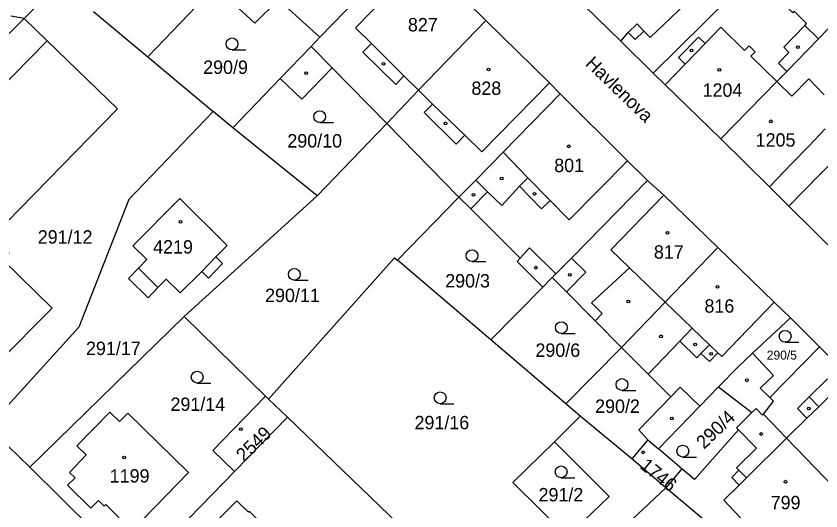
# Model space of a CAD drawing. Extents: x -679220 to -673243, y -1075091 to -1066557.
# Drawn here: x -676221 to -676118.6, y -1072209.4 to -1072146.6 of the extents above; entities that cross this region are included whole.
import ezdxf

# ---------------------------------------------------------------- set-up
doc = ezdxf.new("R2010")
doc.units = 0
for name, color, linetype in [('Hranice parcel', 7, 'Continuous'), ('Parcelní čísla', 7, 'Continuous'), ('Pop  PČ popisy', 7, 'Continuous'), ('Vnitřní kresba', 7, 'Continuous'), ('Značky budov', 7, 'Continuous'), ('Značky kultur', 7, 'Continuous')]:
    doc.layers.add(name, color=color, linetype=linetype)

msp = doc.modelspace()

# ---------------------------------------------------------------- linework, layer by layer
at = {"layer": 'Hranice parcel'}
for p, q in [((-676171, -1072137.54), (-676182.33, -1072149.26)), ((-676219.95, -1072146.87), (-676215.59, -1072142.43)), ((-676204.23, -1072151.76), (-676195.64, -1072142.82)), ((-676139.96, -1072153.8), (-676128.56, -1072142.56)), ((-676211.14, -1072145.98), (-676204.23, -1072151.76)), ((-676116.58, -1072147.02), (-676118.96, -1072149.46)), ((-676204.23, -1072151.76), (-676195.92, -1072158.68)), ((-676193.42, -1072160.74), (-676187.38, -1072154.49)), ((-676193.42, -1072160.74), (-676195.92, -1072158.68)), ((-676182.71, -1072169.41), (-676193.42, -1072160.74)), ((-676173.85, -1072160.2), (-676182.71, -1072169.41)), ((-676164.67, -1072169.55), (-676173.85, -1072160.2)), ((-676182.71, -1072169.41), (-676199.6, -1072184.73)), ((-676172.49, -1072177.56), (-676164.67, -1072169.55)), ((-676114.32, -1072179), (-676122.73, -1072170.71)), ((-676160.6, -1072187.71), (-676172.49, -1072177.56)), ((-676153.99, -1072180.99), (-676152.8, -1072179.78)), ((-676160.6, -1072187.71), (-676153.99, -1072180.99)), ((-676199.6, -1072184.73), (-676219.22, -1072203.87)), ((-676199.6, -1072184.73), (-676189.24, -1072194.84)), ((-676127.33, -1072189.39), (-676122.5, -1072184.89)), ((-676122.5, -1072184.89), (-676118.83, -1072188.57)), ((-676151.09, -1072195.83), (-676160.6, -1072187.71)), ((-676143.98, -1072188.65), (-676151.09, -1072195.83)), ((-676131.67, -1072193.67), (-676127.41, -1072196.92)), ((-676189.24, -1072194.84), (-676188.86, -1072195.21)), ((-676188.86, -1072195.21), (-676186.48, -1072197.53)), ((-676149.25, -1072197.4), (-676151.09, -1072195.83)), ((-676193.21, -1072204.43), (-676186.48, -1072197.53)), ((-676149.25, -1072197.4), (-676152.53, -1072200.63)), ((-676142.69, -1072202.8), (-676149.25, -1072197.4)), ((-676219.22, -1072203.87), (-676224.5, -1072198.75)), ((-676140.66, -1072200.39), (-676142.69, -1072202.8)), ((-676140.66, -1072200.39), (-676139.3, -1072201.54)), ((-676136.31, -1072204.07), (-676139.3, -1072201.54)), ((-676138.34, -1072206.48), (-676142.69, -1072202.8)), ((-676205.67, -1072217.2), (-676219.22, -1072203.87)), ((-676205.67, -1072217.2), (-676193.21, -1072204.43)), ((-676136.31, -1072204.07), (-676138.34, -1072206.48)), ((-676122.41, -1072219.9), (-676138.34, -1072206.48))]:
    msp.add_line(p, q, dxfattribs=at)
for points in [[(-676171, -1072137.54), (-676169.21, -1072139.25), (-676161.24, -1072147.11)], [(-676118.96, -1072149.46), (-676120.69, -1072147.75), (-676120.47, -1072147.52), (-676122.04, -1072145.93), (-676122.23, -1072146.15), (-676122.9, -1072145.47), (-676122.69, -1072145.28), (-676126.97, -1072140.99)], [(-676195.64, -1072142.82), (-676190.61, -1072147.46), (-676187.6, -1072144.46), (-676182.33, -1072149.26)], [(-676148.74, -1072145.24), (-676144.1, -1072149.74), (-676139.96, -1072153.8)], [(-676219.95, -1072146.87), (-676237.05, -1072163.9), (-676236.34, -1072164.6), (-676242.74, -1072171.08), (-676245.38, -1072174.32), (-676244.93, -1072177.99), (-676242.47, -1072175.5), (-676240.49, -1072177.48), (-676243.23, -1072180.25), (-676228.03, -1072195.27)], [(-676228.03, -1072195.27), (-676223.34, -1072190.59), (-676216.38, -1072183.67), (-676222.64, -1072177.53), (-676221.83, -1072176.7), (-676223.99, -1072174.59), (-676208.07, -1072158.35), (-676217, -1072149.7), (-676219.95, -1072146.87)], [(-676173.85, -1072160.2), (-676169.79, -1072155.99), (-676161.24, -1072147.11)], [(-676161.24, -1072147.11), (-676153.17, -1072155.05), (-676151.81, -1072156.45)], [(-676182.33, -1072149.26), (-676183.45, -1072150.42), (-676187.38, -1072154.49)], [(-676131.37, -1072162.17), (-676124.26, -1072154.89), (-676122.99, -1072153.59), (-676118.96, -1072149.46)], [(-676187.38, -1072154.49), (-676184.65, -1072157.13), (-676180.78, -1072153.14), (-676173.85, -1072160.2)], [(-676139.96, -1072153.8), (-676138.45, -1072155.3), (-676131.37, -1072162.17)], [(-676151.81, -1072156.45), (-676159.06, -1072163.86), (-676162.53, -1072167.4), (-676164.67, -1072169.55)], [(-676151.81, -1072156.45), (-676143.23, -1072164.95), (-676140.68, -1072167.47)], [(-676122.73, -1072170.71), (-676112.65, -1072160.42), (-676111.29, -1072159.03), (-676110.05, -1072157.72)], [(-676195.92, -1072158.68), (-676206.62, -1072169.88), (-676212.97, -1072186.08), (-676224.5, -1072198.75)], [(-676131.37, -1072162.17), (-676125.17, -1072168.27), (-676122.73, -1072170.71)], [(-676152.8, -1072179.78), (-676152.34, -1072179.32), (-676150.36, -1072177.31), (-676140.68, -1072167.47)], [(-676140.68, -1072167.47), (-676138.62, -1072169.32), (-676131.77, -1072175.96)], [(-676204.18, -1072182.37), (-676206.66, -1072179.88), (-676205.42, -1072178.57), (-676204.36, -1072177.5), (-676206.13, -1072175.75), (-676200.14, -1072169.72), (-676194.13, -1072175.69), (-676195.58, -1072177.16), (-676194.72, -1072178.01), (-676196.51, -1072179.84), (-676197.36, -1072178.99), (-676200.09, -1072181.72), (-676201.88, -1072179.97), (-676202.93, -1072181.04), (-676204.18, -1072182.37)], [(-676164.67, -1072169.55), (-676163.17, -1072171.05), (-676156.88, -1072177.31), (-676157.28, -1072177.76), (-676153.99, -1072180.99)], [(-676131.77, -1072175.96), (-676138.45, -1072182.9), (-676143.98, -1072188.65)], [(-676131.77, -1072175.96), (-676124.58, -1072182.9), (-676122.5, -1072184.89)], [(-676188.86, -1072195.21), (-676172.84, -1072177.27), (-676172.49, -1072177.56)], [(-676152.8, -1072179.78), (-676151, -1072181.59), (-676147.35, -1072185.26), (-676143.98, -1072188.65)], [(-676118.83, -1072188.57), (-676125.13, -1072195.02), (-676126.35, -1072193.81), (-676124.67, -1072192.24), (-676127.33, -1072189.39)], [(-676118.83, -1072188.57), (-676115.04, -1072192.36), (-676107.7, -1072199.66)], [(-676143.98, -1072188.65), (-676140.61, -1072192.04), (-676137.71, -1072194.95), (-676141.78, -1072199.14), (-676140.66, -1072200.39)], [(-676127.33, -1072189.39), (-676129.18, -1072191.11), (-676131.67, -1072193.67)], [(-676139.3, -1072201.54), (-676134.04, -1072196.12), (-676131.67, -1072193.67)], [(-676193.21, -1072204.43), (-676195.97, -1072201.74), (-676189.24, -1072194.84)], [(-676115.76, -1072207.69), (-676123, -1072200.2), (-676125.95, -1072197.15), (-676126.05, -1072197.24), (-676126.89, -1072196.4), (-676127.41, -1072196.92)], [(-676211.47, -1072209.07), (-676214.42, -1072206.17), (-676213.47, -1072205.21), (-676214.18, -1072204.52), (-676212.05, -1072202.31), (-676213.25, -1072201.15), (-676209.05, -1072196.86), (-676207.81, -1072198.07), (-676206.77, -1072197), (-676199.04, -1072204.56), (-676206.26, -1072211.94), (-676209.56, -1072208.59), (-676209.77, -1072208.81), (-676210.5, -1072208.09), (-676211.47, -1072209.07)], [(-676186.48, -1072197.53), (-676167.7, -1072215.6), (-676169.65, -1072217.48)], [(-676127.41, -1072196.92), (-676129.38, -1072198.88), (-676129.14, -1072199.12), (-676134.72, -1072205.41), (-676136.31, -1072204.07)], [(-676152.53, -1072200.63), (-676157.8, -1072205.82), (-676150.87, -1072212.69)], [(-676152.53, -1072200.63), (-676145.55, -1072207.57), (-676150.87, -1072212.69)], [(-676191.42, -1072209.6), (-676192.91, -1072208.12), (-676197.8, -1072213.04), (-676197.56, -1072213.28), (-676197.7, -1072213.43), (-676196.42, -1072214.7), (-676199.85, -1072218.15), (-676198.3, -1072219.68), (-676198.54, -1072219.92), (-676194.63, -1072223.88), (-676194.38, -1072223.63), (-676194.15, -1072223.86), (-676194.16, -1072224.35), (-676193.21, -1072225.31), (-676191.78, -1072225.35), (-676190.88, -1072224.39), (-676190.84, -1072223.89), (-676184.05, -1072216.69), (-676184.2, -1072216.54), (-676183.12, -1072215.44), (-676187.8, -1072210.79), (-676188.89, -1072211.89), (-676191.31, -1072209.49), (-676191.42, -1072209.6)]]:
    msp.add_lwpolyline(points, dxfattribs=at)
at = {"layer": 'Vnitřní kresba'}
for p, q in [((-676169.21, -1072139.25), (-676177.82, -1072148.04)), ((-676140.37, -1072149.29), (-676134.74, -1072143.91)), ((-676219.95, -1072146.87), (-676221.63, -1072146.59)), ((-676143.13, -1072148.64), (-676142.01, -1072147.57)), ((-676142.01, -1072147.57), (-676141.14, -1072148.48)), ((-676177.82, -1072148.04), (-676175.8, -1072150.03)), ((-676144.1, -1072149.74), (-676143.13, -1072148.64)), ((-676142.26, -1072149.55), (-676143.13, -1072148.64)), ((-676141.14, -1072148.48), (-676142.26, -1072149.55)), ((-676141.14, -1072148.48), (-676140.37, -1072149.29)), ((-676131.36, -1072147.98), (-676133.36, -1072150.05)), ((-676128.34, -1072150.92), (-676131.36, -1072147.98)), ((-676123.38, -1072150.53), (-676120.69, -1072147.75)), ((-676234, -1072166.91), (-676217, -1072149.7)), ((-676136.75, -1072151.83), (-676134.19, -1072149.23)), ((-676134.19, -1072149.23), (-676133.36, -1072150.05)), ((-676180.78, -1072153.14), (-676183.45, -1072150.42)), ((-676175.8, -1072150.03), (-676176.88, -1072151.14)), ((-676171.65, -1072154.17), (-676175.8, -1072150.03)), ((-676133.36, -1072150.05), (-676135.9, -1072152.67)), ((-676127.76, -1072150.36), (-676128.34, -1072150.92)), ((-676127, -1072151.11), (-676127.76, -1072150.36)), ((-676122.71, -1072151.21), (-676123.38, -1072150.53)), ((-676176.88, -1072151.14), (-676172.7, -1072155.24)), ((-676127.57, -1072151.67), (-676127, -1072151.11)), ((-676124.26, -1072154.89), (-676127.57, -1072151.67)), ((-676124.04, -1072152.54), (-676122.71, -1072151.21)), ((-676135.9, -1072152.67), (-676138.45, -1072155.3)), ((-676135.9, -1072152.67), (-676136.75, -1072151.83)), ((-676122.99, -1072153.59), (-676124.04, -1072152.54)), ((-676172.7, -1072155.24), (-676171.65, -1072154.17)), ((-676171.65, -1072154.17), (-676169.79, -1072155.99)), ((-676120.18, -1072154.52), (-676122.35, -1072156.75)), ((-676118.21, -1072156.55), (-676120.18, -1072154.52)), ((-676161.77, -1072163.81), (-676153.17, -1072155.05)), ((-676122.35, -1072156.75), (-676124.26, -1072154.89)), ((-676169.79, -1072155.99), (-676168.01, -1072157.74)), ((-676168.01, -1072157.74), (-676169.07, -1072158.82)), ((-676163.91, -1072161.71), (-676168.01, -1072157.74)), ((-676169.07, -1072158.82), (-676165, -1072162.82)), ((-676120.2, -1072163.09), (-676118.09, -1072160.88)), ((-676165, -1072162.82), (-676163.91, -1072161.71)), ((-676163.91, -1072161.71), (-676161.77, -1072163.81)), ((-676155.9, -1072167.1), (-676159.06, -1072163.86)), ((-676120.2, -1072163.09), (-676122.37, -1072165.35)), ((-676150.67, -1072172.46), (-676143.23, -1072164.95)), ((-676125.17, -1072168.27), (-676122.37, -1072165.35)), ((-676161.02, -1072168.88), (-676162.53, -1072167.4)), ((-676156.97, -1072168.15), (-676155.9, -1072167.1)), ((-676153.08, -1072169.99), (-676155.9, -1072167.1)), ((-676163.17, -1072171.05), (-676161.02, -1072168.88)), ((-676161.02, -1072168.88), (-676159.23, -1072170.63)), ((-676159.23, -1072170.63), (-676156.97, -1072168.15)), ((-676156.97, -1072168.15), (-676154.15, -1072171.04)), ((-676154.15, -1072171.04), (-676153.08, -1072169.99)), ((-676153.08, -1072169.99), (-676150.67, -1072172.46)), ((-676145.34, -1072176.25), (-676138.62, -1072169.32)), ((-676156.88, -1072177.31), (-676155.7, -1072176.01)), ((-676155.7, -1072176.01), (-676152.34, -1072179.32)), ((-676142.98, -1072178.53), (-676145.34, -1072176.25)), ((-676197.36, -1072178.99), (-676195.58, -1072177.16)), ((-676150.36, -1072177.31), (-676148.54, -1072179.1)), ((-676202.93, -1072181.04), (-676205.42, -1072178.57)), ((-676148.54, -1072179.1), (-676151, -1072181.59)), ((-676147.82, -1072182.98), (-676142.98, -1072178.53)), ((-676142.98, -1072178.53), (-676138.45, -1072182.9)), ((-676146.45, -1072184.36), (-676147.82, -1072182.98)), ((-676135.01, -1072186.21), (-676138.45, -1072182.9)), ((-676131.26, -1072189.82), (-676124.58, -1072182.9)), ((-676147.35, -1072185.26), (-676146.45, -1072184.36)), ((-676135.01, -1072186.21), (-676136.59, -1072187.86)), ((-676132.83, -1072188.31), (-676135.01, -1072186.21)), ((-676136.59, -1072187.86), (-676140.61, -1072192.04)), ((-676136.59, -1072187.86), (-676134.4, -1072189.96)), ((-676133.9, -1072189.43), (-676132.83, -1072188.31)), ((-676131.75, -1072189.35), (-676132.83, -1072188.31)), ((-676134.4, -1072189.96), (-676133.9, -1072189.43)), ((-676132.82, -1072190.46), (-676133.9, -1072189.43)), ((-676131.75, -1072189.35), (-676132.82, -1072190.46)), ((-676131.26, -1072189.82), (-676131.75, -1072189.35)), ((-676120.14, -1072194.95), (-676117.82, -1072192.66)), ((-676136.52, -1072193.72), (-676137.71, -1072194.95)), ((-676134.04, -1072196.12), (-676136.52, -1072193.72)), ((-676118.92, -1072196.18), (-676116.61, -1072193.9)), ((-676125.95, -1072197.15), (-676124.68, -1072195.46)), ((-676124.68, -1072195.46), (-676125.13, -1072195.02)), ((-676121.63, -1072196.42), (-676120.14, -1072194.95)), ((-676118.92, -1072196.18), (-676120.14, -1072194.95)), ((-676120.42, -1072197.65), (-676121.63, -1072196.42)), ((-676120.42, -1072197.65), (-676118.92, -1072196.18)), ((-676123, -1072200.2), (-676120.42, -1072197.65)), ((-676129.14, -1072199.12), (-676126.82, -1072201.45)), ((-676128.11, -1072205.23), (-676123, -1072200.2)), ((-676126.82, -1072201.45), (-676129.37, -1072203.96)), ((-676129.07, -1072204.26), (-676129.98, -1072205.16)), ((-676129.37, -1072203.96), (-676129.07, -1072204.26)), ((-676129.07, -1072204.26), (-676128.11, -1072205.23)), ((-676129.98, -1072205.16), (-676129.02, -1072206.13)), ((-676129.02, -1072206.13), (-676128.11, -1072205.23)), ((-676146.7, -1072214.3), (-676138.34, -1072206.48)), ((-676129.02, -1072206.13), (-676130.98, -1072208.06)), ((-676130.98, -1072208.06), (-676123.79, -1072215.59))]:
    msp.add_line(p, q, dxfattribs=at)
at = {"layer": 'Značky budov'}
for centre in [(-676121.59, -1072150.5), (-676135.09, -1072150.93), (-676174.26, -1072152.63), (-676184.09, -1072153.83), (-676160.92, -1072153.34), (-676131.56, -1072153.4), (-676125.02, -1072159.94), (-676166.37, -1072160.21), (-676150.71, -1072163.11), (-676159.23, -1072167.19), (-676162.82, -1072169.26), (-676155.06, -1072169.13), (-676200.07, -1072172.71), (-676138.16, -1072174.09), (-676154.88, -1072178.52), (-676150.58, -1072179.44), (-676131.8, -1072180.95), (-676143.13, -1072182.81), (-676138.98, -1072187.25), (-676134.64, -1072188.27), (-676132.6, -1072189.47), (-676128.05, -1072192.83), (-676120.18, -1072196.41), (-676137.61, -1072197.67), (-676192.4, -1072199.05), (-676126.23, -1072199.65), (-676141.24, -1072201.98), (-676207.24, -1072202.63), (-676123.16, -1072205.71)]:
    msp.add_circle(centre, 0.175, dxfattribs=at)
at = {"layer": 'Značky kultur'}
for p, q in [((-676193.51, -1072150.85), (-676191.76, -1072150.85)), ((-676182.36, -1072160.09), (-676180.61, -1072160.09)), ((-676163, -1072177.75), (-676161.25, -1072177.75)), ((-676185.59, -1072180.12), (-676183.84, -1072180.12)), ((-676151.65, -1072186.89), (-676149.9, -1072186.89)), ((-676123.19, -1072187.99), (-676121.44, -1072187.99)), ((-676197.94, -1072193.18), (-676196.19, -1072193.18)), ((-676143.93, -1072194.12), (-676142.18, -1072194.12)), ((-676167.05, -1072195.8), (-676165.3, -1072195.8)), ((-676136.2, -1072202.58), (-676134.45, -1072202.58)), ((-676151.67, -1072205.21), (-676149.92, -1072205.21))]:
    msp.add_line(p, q, dxfattribs=at)
for centre in [(-676193.51, -1072150.1), (-676182.36, -1072159.34), (-676163, -1072177), (-676185.59, -1072179.37), (-676151.65, -1072186.14), (-676123.19, -1072187.24), (-676197.94, -1072192.43), (-676143.93, -1072193.37), (-676167.05, -1072195.05), (-676136.2, -1072201.83), (-676151.67, -1072204.46)]:
    msp.add_circle(centre, 0.75, dxfattribs=at)

# ---------------------------------------------------------------- texts
at = {"layer": 'Parcelní čísla'}
for s, height, p in [('827', 1.7, (-676171.15, -1072148.51)), ('290/9', 1.7, (-676197.18, -1072153.91)), ('828', 1.7, (-676163.08, -1072156.58)), ('1204', 1.7, (-676133.69, -1072156.82)), ('290/10', 1.7, (-676186.48, -1072163.26)), ('1205', 1.7, (-676126.94, -1072163.15)), ('801', 1.7, (-676152.55, -1072166.38)), ('291/12', 1.7, (-676218.21, -1072175.47)), ('4219', 1.7, (-676203.54, -1072176.73)), ('817', 1.7, (-676139.88, -1072177.38)), ('290/3', 1.7, (-676166.41, -1072181.04)), ('290/11', 1.7, (-676189.31, -1072182.89)), ('816', 1.7, (-676133.45, -1072184.24)), ('291/17', 1.7, (-676212.08, -1072189.62)), ('290/6', 1.7, (-676154.94, -1072189.85)), ('290/5', 1.14, (-676125.52, -1072190.2)), ('291/14', 1.7, (-676201.34, -1072196.72)), ('290/2', 1.7, (-676147.35, -1072196.97)), ('291/16', 1.7, (-676170.31, -1072199.05)), ('1199', 1.7, (-676209.06, -1072205.82)), ('291/2', 1.7, (-676154.54, -1072208.21)), ('799', 1.7, (-676125.03, -1072209.21))]:
    msp.add_text(s, height=height, dxfattribs=at).set_placement(p)
for s, rotation, p in [('290/4', 44, (-676133.5, -1072201.66)), ('2549', 44, (-676192, -1072203.27)), ('1746', 321, (-676141.77, -1072203.9))]:
    msp.add_text(s, height=1.7, rotation=rotation, dxfattribs=at).set_placement(p)
at = {"layer": 'Pop  PČ popisy'}
msp.add_text('Havlenova', height=1.7, rotation=316, dxfattribs=at).set_placement((-676148.7, -1072152.74))

doc.saveas('drawing.dxf')
